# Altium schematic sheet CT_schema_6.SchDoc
size 278 x 170 mm
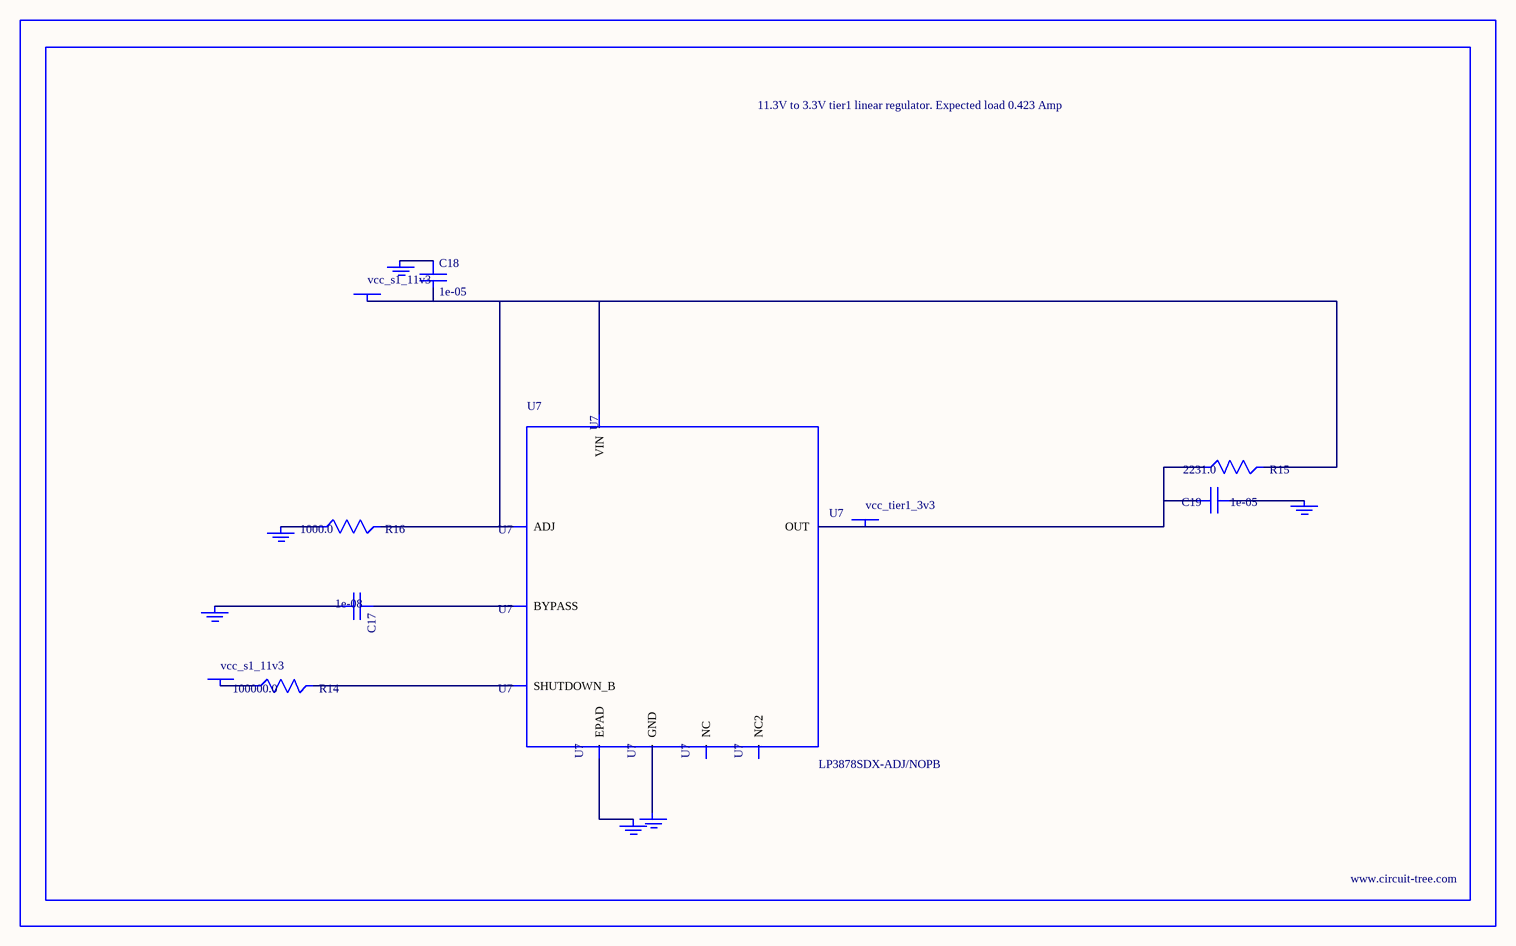
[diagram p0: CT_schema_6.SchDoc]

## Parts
BORDER5  (no value)
C17  1e-08  [C0402]
C18  1e-05  [C1210]
C19  1e-05  [C1210]
GND_INSTANCE_5_0  (no value)
GND_INSTANCE_5_1  (no value)
GND_INSTANCE_5_2  (no value)
GND_INSTANCE_5_3  (no value)
GND_INSTANCE_5_4  (no value)
GND_INSTANCE_5_5  (no value)
POWER_INSTANCE_5_0  vcc_s1_11v3
POWER_INSTANCE_5_1  vcc_s1_11v3
POWER_INSTANCE_5_2  vcc_tier1_3v3
R14  100000.0  [R0603]
R15  2231.0  [R0603]
R16  1000.0  [R0603]
U7  LP3878SDX-ADJ/NOPB  [WSON-8]

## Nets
NetC17_1: C17.1 U7.1(BYPASS)
NetC17_2: C17.2 GND_INSTANCE_5_0.0(GND)
NetC18_1: C18.1 GND_INSTANCE_5_1.0(GND)
NetC18_2: C18.2 POWER_INSTANCE_5_0.0(PWR) R15.2 R16.2 U7.4(VIN) U7.6(ADJ)
NetC19_1: C19.1 GND_INSTANCE_5_2.0(GND)
NetC19_2: C19.2 POWER_INSTANCE_5_2.0(PWR) R15.1 U7.5(OUT)
NetGND_INSTANCE_5_3_0: GND_INSTANCE_5_3.0(GND) R16.1
NetGND_INSTANCE_5_4_0: GND_INSTANCE_5_4.0(GND) U7.PAD(EPAD)
NetGND_INSTANCE_5_5_0: GND_INSTANCE_5_5.0(GND) U7.3(GND)
NetPOWER_INSTANCE_5_1_0: POWER_INSTANCE_5_1.0(PWR) R14.1
NetR14_2: R14.2 U7.8(SHUTDOWN_B)

Not connected (* = marked no-connect by the designer): U7 2(NC) 7(NC2)

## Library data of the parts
BORDER5 = BORDER_PAGE5
C17 = C0402C103K3RAC
C18 = C1210C106K5PACTU
C19 = GRM32DR61E106MA12L
GND_INSTANCE_5_0-GND_INSTANCE_5_5 = GND
POWER_INSTANCE_5_0-POWER_INSTANCE_5_2 = PWR
R14 = RC0603JR-07100KL
R15 = R15
R16 = RC0603JR-071KL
